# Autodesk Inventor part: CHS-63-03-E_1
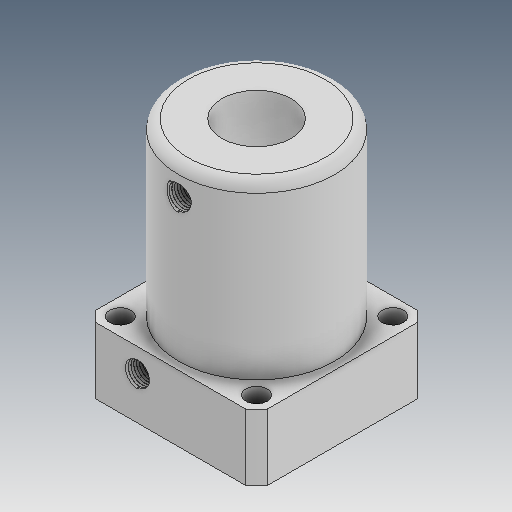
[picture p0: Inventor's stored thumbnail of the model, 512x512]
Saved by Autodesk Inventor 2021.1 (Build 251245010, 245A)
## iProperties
Created: 2019-05
Part Number: CHS-63-03-E_1
Material: Ogólny
Document SubType Name: Modeling
Designer: user
Density: 1 g/cm^3
Appearance: Domyślna
Author: user
Revision Number: ÈÎºÎ
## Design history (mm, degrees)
feature "ÊäÈë1"
node "Bryła1"
